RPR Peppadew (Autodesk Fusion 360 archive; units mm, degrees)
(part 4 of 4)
sketch "Sketch185" plane through (0, -2.2015, 0) normal (0, 1, 0) x axis (-1, 0, 0)
  line L1 (9.0125, -12.5) -> (-65.5, -12.5)
  line L2 (13.7, -5) -> (9.0125, -12.5)
  line L3 (15.7, 11) -> (13.7, -5)
  line L4 (13.7, 19) -> (15.7, 11)
  line L5 (6.05, 16.96) -> (13.7, 19)
  line L6 (6.05, 4.95) -> (6.05, 16.96)
  line L7 (3, 4.95) -> (6.05, 4.95)
  line L8 (3, 0) -> (3, 4.95)
  line L9 (-3, 4.95) -> (-3, 0)
  line L10 (-6.05, 4.95) -> (-3, 4.95)
  line L11 (-6.05, 8.0592) -> (-6.05, 4.95)
  line L12 (-51.698, 1.5605) -> (-13.5118, 11.7435)
  line L13 (-65.5, -2.12) -> (-63.6343, -1.6225)
  line L14 (-65.5, -12.5) -> (-65.5, -2.12)
  line L15 (-13.1998, -11.5004) -> (-37.1998, -11.5004)
  line L16 (-9, -11.5004) -> (-13.1998, -11.5004)
  line L17 (-19, -11.5004) -> (-9, -11.5004)
  line L18 (-67, -11.5004) -> (-19, -11.5004)
  line L19 (-64.5, -11.5004) -> (-67, -11.5004)
  line L20 (-64.5, -11.5004) -> (-61.5, -11.5004)
  line L21 (-67, -11.5004) -> (-64.5, -11.5004)
  line L22 (-64.5, -11.5004) -> (-67, -11.5004)
  line L23 (-64.5, -11.5004) -> (-61.5, -11.5004)
  line L24 (-67, -11.5004) -> (-64.5, -11.5004)
  line L25 (-64.5, -11.5004) -> (-67, -11.5004)
  line L26 (-61.6716, -11.5004) -> (-64.5, -11.5004)
  line L27 (-37.1998, -11.5004) -> (-61.6716, -11.5004)
  line L28 (-61.5, -11.5004) -> (-37.1998, -11.5004)
  line L29 (-37.1998, -11.5004) -> (-61.5, -11.5004)
  line L30 (-37.1998, -11.5004) -> (-52.1998, -11.5004)
  line L31 (-37.1998, -7.5004) -> (-37.1998, -11.5004)
  line L32 (-52.1998, -7.5004) -> (-37.1998, -7.5004)
  line L33 (-52.1998, -11.5004) -> (-52.1998, -7.5004)
  line L34 (-36.3091, 0.4895) -> (-60.4649, -5.952)
  line L35 (-35.1998, -9) -> (-36.3091, 0.4895)
  line L36 (-37.1998, -11) -> (-35.1998, -9)
  line L37 (-37.1998, -11.5004) -> (-37.1998, -11)
  line L38 (-61.6716, -11.5004) -> (-37.1998, -11.5004)
  line L39 (-61.6716, -5.952) -> (-61.6716, -11.5004)
  line L40 (-60.4649, -5.952) -> (-61.6716, -5.952)
  arc A1 centre (0, 0) radius 3 clockwise from (3, 0) to (-3, 0)
  arc A2 centre (-8.1677, 13.1686) radius 5.5309 clockwise from (-6.05, 8.0592) to (-13.5118, 11.7435)
  arc A3 centre (-57.6661, -0.031) radius 6.1767 clockwise from (-51.698, 1.5605) to (-63.6343, -1.6225)
  point P31 (-52.1998, -11.5004)
  point P39 (-37.1998, -11.5004)
  point P32 (-37.1998, -11.5004)
  point P34 (-52.1998, -7.5004)
  horizontal L30
  vertical L31
  horizontal L32
  vertical L33
  coincident L29 P31
  coincident L31 P39
  dimension "d1044" distance P31 P32 = 15
  dimension "d1045" distance P31 P34 = 4
extrude "Extrude208" cut sketch "Sketch185" profile of L18 L27 L28 L29 L30 L31 L32 L33 L37 L38 against normal blind 4
extrude "Extrude13" cut of existing geometry blind -5
sketch "Sketch186" plane through (0, -63.8015, 0) normal (0, -1, 0) x axis (1, 0, 0)
  line L1 (28.7786, 11.5689) -> (70.8397, -1.4895)
  line L2 (29.0751, 12.524) -> (28.7786, 11.5689)
  line L3 (18.2711, 15.8782) -> (29.0751, 12.524)
  line L4 (24.8291, 12.2935) -> (17.8849, 13.9394)
  line L5 (17.1181, 8.8069) -> (24.2402, 8.3515)
  line L6 (30.0172, 6.8637) -> (16.9116, 6.8259)
  line L7 (69.0672, -2.4859) -> (30.0172, 6.8637)
  line L8 (70.8397, -1.4895) -> (69.0672, -2.4859)
  arc A1 centre (18.1228, 15.4007) radius 0.5 clockwise from (17.6384, 15.2768) to (18.2711, 15.8782)
  arc A2 centre (7.95, 12.8) radius 10 clockwise from (17.6384, 15.2768) to (17.8849, 13.9394)
  arc A3 centre (24.3678, 10.3474) radius 2 clockwise from (24.8291, 12.2935) to (24.2402, 8.3515)
  arc A4 centre (7.95, 12.8) radius 10 clockwise from (17.1181, 8.8069) to (16.4834, 7.5865)
  arc A5 centre (16.9101, 7.3259) radius 0.5 clockwise from (16.9116, 6.8259) to (16.4834, 7.5865)
sketch "Sketch187" plane through (5.806, 0, 18.7011) normal (0.2965, 0, 0.955) x axis (0.955, 0, -0.2965)
  line L1 (68.0958, -63.8015) -> (24.0543, -63.8015)
  line L2 (68.0958, -39.8015) -> (68.0958, -63.8015)
  line L3 (24.0543, -39.8015) -> (68.0958, -39.8015)
  line L4 (24.0543, -63.8015) -> (24.0543, -39.8015)
  line L5 (63.0958, -63.8015) -> (68.0958, -63.8015)
  line L6 (63.0958, -39.8015) -> (63.0958, -63.8015)
  line L7 (68.0958, -39.8015) -> (63.0958, -39.8015)
  line L8 (68.0958, -63.8015) -> (68.0958, -39.8015)
  circle C1 centre (55.5543, -43.8015) radius 1.25
  circle C2 centre (55.5543, -59.8015) radius 1.25
  circle C3 centre (30.5543, -43.8015) radius 1.25
  circle C4 centre (30.5543, -59.8015) radius 1.25
  point P7 (68.0958, -63.8015)
  point P10 (68.0958, -63.8015)
  point P11 (63.0958, -63.8015)
  horizontal L5
  vertical L6
  horizontal L7
  vertical L8
  coincident P7 P10
  dimension "d1051" distance P10 P11 = 5
extrude "Extrude209" cut sketch "Sketch187" profile of L1 L2 L3 L5 L6 L7 L8 against normal blind 5
extrude "Extrude210" cut of existing geometry blind -1.8
extrude "Extrude211" cut of existing geometry blind -1.8
sketch "Sketch188" plane through (5.806, 0, 18.7011) normal (0.2965, 0, 0.955) x axis (0.955, 0, -0.2965)
  line L1 (63.0958, -39.8015) -> (63.0958, -63.8015)
  line L2 (24.0543, -39.8015) -> (63.0958, -39.8015)
  line L3 (24.0543, -63.8015) -> (24.0543, -39.8015)
  line L4 (63.0958, -63.8015) -> (24.0543, -63.8015)
  circle C1 centre (55.5543, -43.8015) radius 1.25
  circle C2 centre (55.5543, -59.8015) radius 1.25
  circle C3 centre (30.5543, -43.8015) radius 1.25
  circle C4 centre (30.5543, -59.8015) radius 1.25
  circle C5 centre (30.5543, -43.8015) radius 4
  circle C6 centre (55.5543, -43.8015) radius 4
  circle C7 centre (55.5543, -59.8015) radius 4
  circle C8 centre (30.5543, -59.8015) radius 4
  concentric C3 C5
  tangent L2 C5
  concentric C1 C6
  tangent L2 C6
  concentric C2 C7
  tangent L4 C7
  concentric C4 C8
  tangent L4 C8
sketch "Sketch189" plane through (0, -63.8015, 0) normal (0, -1, 0) x axis (1, 0, 0)
  line L1 (66.0645, -0.007) -> (65.5559, -1.6452)
  line L2 (28.7786, 11.5689) -> (66.0645, -0.007)
  line L3 (29.0751, 12.524) -> (28.7786, 11.5689)
  line L4 (18.2711, 15.8782) -> (29.0751, 12.524)
  line L5 (24.8291, 12.2935) -> (17.8849, 13.9394)
  line L6 (17.1181, 8.8069) -> (24.2402, 8.3515)
  line L7 (30.0172, 6.8637) -> (16.9116, 6.8259)
  line L8 (65.5559, -1.6452) -> (30.0172, 6.8637)
  line L9 (56.9873, 0.4063) -> (59.4239, -0.1771)
  line L10 (60.0559, 1.8585) -> (57.6683, 2.5997)
  line L11 (32.6214, 6.2402) -> (35.058, 5.6568)
  line L12 (36.1801, 9.271) -> (33.7925, 10.0123)
  line L13 (58.5734, -2.9167) -> (65.5559, -1.6452)
  line L14 (26.3203, 7.0967) -> (58.5734, -2.9167)
  arc A1 centre (18.1228, 15.4007) radius 0.5 clockwise from (17.6384, 15.2768) to (18.2711, 15.8782)
  arc A2 centre (7.95, 12.8) radius 10 clockwise from (17.6384, 15.2768) to (17.8849, 13.9394)
  arc A3 centre (24.3678, 10.3474) radius 2 clockwise from (24.8291, 12.2935) to (24.2402, 8.3515)
  arc A4 centre (7.95, 12.8) radius 10 clockwise from (17.1181, 8.8069) to (16.4834, 7.5865)
  arc A5 centre (16.9101, 7.3259) radius 0.5 clockwise from (16.9116, 6.8259) to (16.4834, 7.5865)
  point P2 (65.5559, -1.6452)
  point P28 (65.5559, -1.6452)
  point P22 (60.0559, 1.8585)
  point P27 (58.5734, -2.9167)
  coincident P2 P28
  parallel L2 L14
  dimension "d1062" distance P22 P27 = 5
extrude "Extrude16" add sketch "Sketch189" profile of L7 L8 L9 L11 L13 L14 against normal blind 24
extrude "Extrude17" cut of existing geometry blind -11
sketch "Sketch190" plane through (5.8632, 0, 18.6946) normal (-0.2993, 0, -0.9542) x axis (-0.9542, 0, 0.2993)
  line L1 (-109.0121, -39.8015) -> (-24.0121, -39.8015)
  line L2 (-109.0121, -63.8015) -> (-109.0121, -39.8015)
  line L3 (-24.0121, -63.8015) -> (-109.0121, -63.8015)
  line L4 (-24.0121, -39.8015) -> (-24.0121, -63.8015)
  line L5 (-56.7619, -44.4621) -> (-56.7619, -59.1408)
  line L6 (-56.7619, -39.8015) -> (-56.7619, -43.1408)
  line L7 (-63.0439, -39.8015) -> (-56.7619, -39.8015)
  line L8 (-63.0439, -63.8015) -> (-63.0439, -39.8015)
  line L9 (-56.7619, -63.8015) -> (-63.0439, -63.8015)
  line L10 (-56.7619, -60.4621) -> (-56.7619, -63.8015)
  line L11 (-24.0879, -56.8015) -> (-102, -56.8015)
  line L12 (-24.0879, -46.8015) -> (-24.0879, -56.8015)
  line L13 (-102, -46.8015) -> (-24.0879, -46.8015)
  line L14 (-102, -56.8015) -> (-102, -46.8015)
  line L15 (-24.0879, -46.8015) -> (-102, -56.8015)
  line L16 (-102, -46.8015) -> (-24.0879, -56.8015)
  line L17 (-104, -44.8015) -> (-22.0879, -44.8015)
  line L18 (-104, -58.8015) -> (-104, -44.8015)
  line L19 (-22.0879, -58.8015) -> (-104, -58.8015)
  line L20 (-22.0879, -44.8015) -> (-22.0879, -58.8015)
  line L21 (-102, -44.8015) -> (-102, -58.8015)
  line L22 (-63.5439, -44.8015) -> (-63.5439, -58.8015)
  circle C1 centre (-30.5121, -43.8015) radius 1.6
  circle C2 centre (-55.5121, -59.8015) radius 1.6
  circle C3 centre (-30.5121, -59.8015) radius 1.6
  circle C4 centre (-55.5121, -43.8015) radius 1.6
  closed curve K1 centre (-55.7332, -59.8015)
  closed curve K2 centre (-55.7332, -43.8015)
  point P24 (-63.0439, -51.8015)
  point P29 (-102, -58.8015)
  point P30 (-102, -44.8015)
  point P31 (-63.5439, -58.8015)
  point P32 (-63.5439, -44.8015)
  point P21 (-24.0879, -56.8015)
  point P22 (-24.0879, -46.8015)
  horizontal L11
  perpendicular L11 L12
  parallel L11 L13
  parallel L12 L14
  coincident L15 P24
  coincident L16 P24
  midpoint L8 P24
  coincident L19 P29
  coincident L17 P30
  perpendicular L17 L21
  coincident L19 P31
  coincident L17 P32
  perpendicular L17 L22
  dimension "d1071" distance P21 P22 = 10
  dimension "d1072" = 2
  dimension "d1075" distance L8 L22 = 0.5
extrude "Extrude2" add sketch "Sketch190" profile of L11 L13 L17 L19 L21 L22 along normal blind 1
chamfer "Chamfer5" distance 7.5
chamfer "Chamfer6" distance 0.5
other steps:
extrude "Extrude2" cut sketch "Sketch163" profile of L7 L18 L19 L21 L22 along normal blind 33.8
extrude "Extrude14" cut sketch "Sketch187" profile of L1 L2 L3 L5 L6 L7 L8 against normal blind 5
fillet "Fillet1" radius 3
base_feature "Base Feature2"
extrude "Extrude181" cut sketch "Sketch151" profile of C9 C13 C16 C19 against normal blind 10
joint_origin "JointOrigin2"
create_component "CreateComponent1"
create_component "CreateComponent1"
joint_origin "JointOrigin2"
create_component "CreateComponent1" sketch "Sketch163"
create_component "CreateComponent2"
create_component "CreateComponent1"
create_component "CreateComponent1"
create_component "CreateComponent2"
create_component "CreateComponent3"
joint_origin "JointOrigin1"
joint_origin "JointOrigin1"
joint_origin "JointOrigin1"
joint_origin "JointOrigin2"
create_component "CreateComponent3"
remove_body "RemoveBody1"
joint_origin "JointOrigin19"
joint_origin "JointOrigin7"
joint_origin "JointOrigin11"
joint_origin "JointOrigin23"
joint_origin "JointOrigin30"
joint_origin "JointOrigin34"
create_component "CreateComponent8"
create_component "CreateComponent9"
remove_body "RemoveBody1"
joint_origin "JointOrigin35"
extrude "Extrude205" cut sketch "Sketch174" profile of C2 L2 L3 L7 L8 L9 L10 against normal blind 1
named bodies: "Ignore", "Shaft", "Thread", "ServoBody", "Signal", "Positive", "Ground", "ServoHorn"

design "RPR 2A5V Booster"
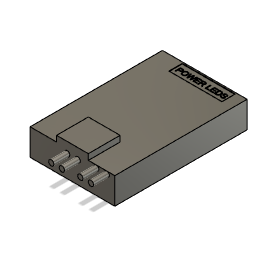
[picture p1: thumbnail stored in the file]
sketch "Sketch1" plane through (0, 0, 0) normal (0, 1, 0) x axis (1, 0, 0)
  line L1 (-8, -12.5) -> (8, -12.5)
  line L2 (-8, 12.5) -> (-8, -12.5)
  line L3 (8, 12.5) -> (-8, 12.5)
  line L4 (8, -12.5) -> (8, 12.5)
  line L5 (-8, 12.5) -> (8, -12.5)
  line L6 (8, 12.5) -> (-8, -12.5)
  point P6 (0, 0)
  point P1 (0, 0)
  point P4 (-8, 12.5)
  point P5 (8, 12.5)
  point P3 (-8, -12.5)
  horizontal L1
  perpendicular L1 L2
  parallel L1 L3
  parallel L2 L4
  coincident L5 P6
  coincident L6 P6
  coincident P1 P6
  dimension "d1" distance P4 P5 = 16
  dimension "d2" distance P3 P4 = 25
extrude "Extrude1" new body sketch "Sketch1" profile of L1 L2 L3 L4 along normal blind 5
sketch "Sketch2" plane through (0, 0, 12.5) normal (0, 0, 1) x axis (1, 0, 0)
  line L1 (8, 0) -> (-8, 0)
  line L2 (8, 5) -> (8, 0)
  line L3 (-8, 5) -> (8, 5)
  line L4 (-8, 0) -> (-8, 5)
  line L5 (3, 1.6) -> (-3, 1.6)
  line L6 (3, 6.1) -> (3, 1.6)
  line L7 (-3, 6.1) -> (3, 6.1)
  line L8 (-3, 1.6) -> (-3, 6.1)
  point P6 (-3, 1.6)
  point P7 (3, 1.6)
  point P9 (-3, 6.1)
  horizontal L5
  vertical L6
  horizontal L7
  vertical L8
  dimension "d5" distance P6 P7 = 6
  dimension "d6" distance P6 P9 = 4.5
  dimension "d7" distance L1 L5 = 1.6
  dimension "d8" distance L2 L6 = 5
  dimension "d9" distance L4 L8 = 5
extrude "Extrude2" add sketch "Sketch2" profile of L3 L5 L6 L7 L8 against normal blind 6
sketch "Sketch3" plane through (-8, 0, 0) normal (-1, 0, 0) x axis (0, 0, 1)
  line L1 (12.5, 0) -> (-12.5, 0)
  line L2 (12.5, 5) -> (12.5, 0)
  line L3 (-12.5, 5) -> (12.5, 5)
  line L4 (-12.5, 0) -> (-12.5, 5)
  line L5 (-7, 4) -> (-10, 4)
  line L6 (-7, 3) -> (-7, 4)
  line L7 (-10, 3) -> (-7, 3)
  line L8 (-10, 4) -> (-10, 3)
  horizontal L5
  vertical L6
  horizontal L7
  vertical L8
extrude "Extrude3" add sketch "Sketch3" profile of L5 L6 L7 L8 along normal blind 1
sketch "Sketch4" plane through (0, 5, 0) normal (0, 1, 0) x axis (-1, 0, 0)
  line L1 (3, 6.5) -> (3, 12.5)
  line L2 (-3, 6.5) -> (3, 6.5)
  line L3 (-3, 12.5) -> (-3, 6.5)
  line L4 (-8, 12.5) -> (-3, 12.5)
  line L5 (-8, -12.5) -> (-8, 12.5)
  line L6 (8, -12.5) -> (-8, -12.5)
  line L7 (8, 12.5) -> (8, -12.5)
  line L8 (3, 12.5) -> (8, 12.5)
  line L9 (4, -9.75) -> (-6, -9.75)
  line L10 (4, -12.25) -> (4, -9.75)
  line L11 (-6, -12.25) -> (4, -12.25)
  line L12 (-6, -9.75) -> (-6, -12.25)
  line L13 (4, -12.25) -> (-6, -9.75)
  line L14 (-6, -12.25) -> (4, -9.75)
  point P14 (-1, -11)
  point P12 (4, -12.25)
  point P13 (-6, -12.25)
  point P11 (4, -9.75)
  horizontal L9
  perpendicular L9 L10
  parallel L9 L11
  parallel L10 L12
  coincident L13 P14
  coincident L14 P14
  dimension "d14" distance P12 P13 = 10
  dimension "d15" distance P11 P12 = 2.5
extrude "Extrude4" cut sketch "Sketch4" profile of L9 L10 L11 L12 against normal blind 0.1
sketch "Sketch5" plane through (0, 0, 12.5) normal (0, 0, 1) x axis (1, 0, 0)
  line L1 (-8, 5) -> (-3, 5)
  line L2 (-8, 0) -> (-8, 5)
  line L3 (8, 0) -> (-8, 0)
  line L4 (8, 5) -> (8, 0)
  line L5 (3, 5) -> (8, 5)
  line L6 (3, 6.1) -> (3, 5)
  line L7 (-3, 6.1) -> (3, 6.1)
  line L8 (-3, 5) -> (-3, 6.1)
  circle C1 centre (-1, 4.1) radius 0.5
  circle C2 centre (1, 4.1) radius 0.5
  circle C3 centre (4.5, 4.5) radius 0.5
  circle C4 centre (6.5, 4.5) radius 0.5
  point P11 (1, 4.1)
  point P10 (-1, 4.1)
  point P12 (4.5, 4.5)
  point P13 (6.5, 4.5)
  tangent L5 C4
  tangent L5 C3
  dimension "d18" diameter C1 = 1
  dimension "d19" diameter C2 = 1
  dimension "d20" diameter C3 = 1
  dimension "d21" diameter C4 = 1
  dimension "d22" distance L7 P11 = 2
  dimension "d23" distance L7 P10 = 2
  dimension "d24" distance P10 P11 = 2
  dimension "d25" distance P12 P13 = 2
  dimension "d26" distance L4 P13 = 1.5
  dimension "d27" distance L6 P11 = 2
extrude "Extrude5" add sketch "Sketch5" profile of C1 C2 C3 C4 along normal blind 3
sketch "Sketch6" plane through (0, 5, 0) normal (0, 1, 0) x axis (-1, 0, 0)
  line L1 (4, -12.25) -> (4, -9.75)
  line L2 (-6, -12.25) -> (4, -12.25)
  line L3 (-6, -9.75) -> (-6, -12.25)
  line L4 (4, -9.75) -> (-6, -9.75)
  line L5 (3, 6.5) -> (3, 12.5)
  line L6 (-3, 6.5) -> (3, 6.5)
  line L7 (-3, 12.5) -> (-3, 6.5)
  line L8 (-4.5, 12.5) -> (-3, 12.5)
  line L9 (-6.5, 12.5) -> (-4.5, 12.5)
  line L10 (-8, 12.5) -> (-6.5, 12.5)
  line L11 (-8, -12.5) -> (-8, 12.5)
  line L12 (8, -12.5) -> (-8, -12.5)
  line L13 (8, 12.5) -> (8, -12.5)
  line L14 (3, 12.5) -> (8, 12.5)
  curve K1
  curve K2
  curve K3
  curve K4
  dimension "d30" Text1-Height = 1
extrude "Extrude6" cut sketch "Sketch6" against normal blind 0.2
sketch "Sketch7" plane through (0, 0, 0) normal (0, -1, 0) x axis (1, 0, 0)
  dimension "d33" = 1.5
extrude "Extrude7" cut sketch "Sketch7" against normal blind 0.1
